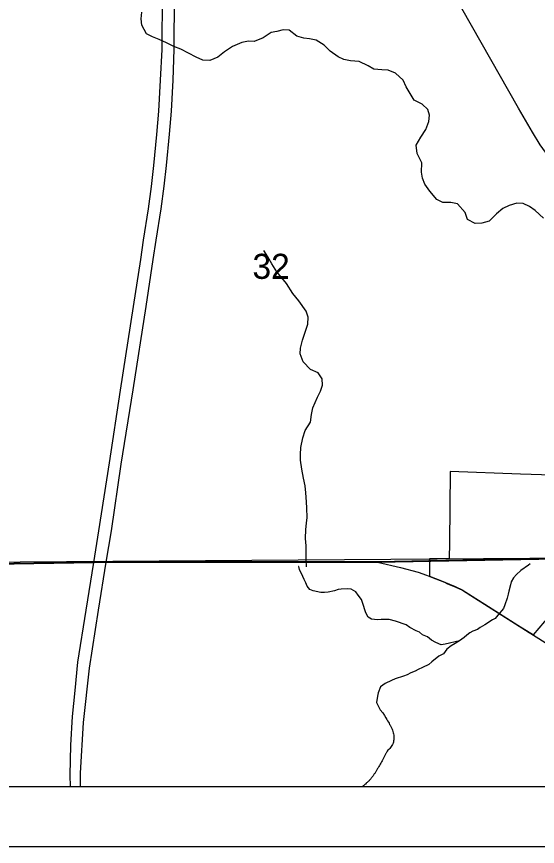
# Model space of a CAD drawing. Extents: x 0 to 36.9, y 0 to 22.
# Drawn here: x 5.318 to 6.188, y 14 to 15.386 of the extents above; entities that cross this region are included whole.
import ezdxf

# ---------------------------------------------------------------- set-up
doc = ezdxf.new("R2010")
doc.units = 0
for name, color, linetype in [('Default', 7, 'Continuous'), ('GM_X_Minor_Lake', 7, 'Continuous'), ('GM_X_Minor_River', 7, 'Continuous'), ('GM_X_Rail_Line', 7, 'Continuous'), ('GM_X_Section', 7, 'Continuous'), ('GM_X_Section_Text', 7, 'Continuous'), ('GM_X_State_Route', 7, 'Continuous'), ('GM_X_Township_Road', 7, 'Continuous'), ('SH_Cut_Line', 7, 'Continuous'), ('SH_Data', 7, 'Continuous')]:
    doc.layers.add(name, color=color, linetype=linetype)

msp = doc.modelspace()

# ---------------------------------------------------------------- linework, layer by layer
at = {"layer": 'Default'}
msp.add_lwpolyline([(6.2478, 14.6189), (6.1594, 14.6218), (6.042, 14.6259), (6.0412, 14.5072), (6.0407, 14.4806), (6.0077, 14.4801), (6.0076, 14.4514), (6.0251, 14.4445), (6.0343, 14.4407), (6.0505, 14.4341), (6.0623, 14.4284), (6.1062, 14.4008), (6.1554, 14.3696), (6.1813, 14.3532), (6.2097, 14.3868)], dxfattribs=at)
at = {"layer": 'GM_X_Minor_Lake'}
msp.add_open_spline([(5.9296, 14.2233), (5.9338, 14.2161), (5.938, 14.209), (5.9422, 14.2018), (5.9444, 14.1981), (5.9458, 14.1939), (5.9471, 14.1896), (5.9482, 14.1859), (5.9484, 14.182), (5.9479, 14.1782), (5.9474, 14.1743), (5.946, 14.1704), (5.9438, 14.1668), (5.9415, 14.1631), (5.9377, 14.1608), (5.9357, 14.1571), (5.9334, 14.1528), (5.9315, 14.1483), (5.9291, 14.144), (5.9262, 14.1388), (5.9232, 14.1337), (5.9202, 14.1286), (5.9179, 14.1247), (5.9155, 14.1209), (5.9128, 14.1172), (5.9096, 14.1126), (5.9056, 14.1087), (5.9014, 14.105), (5.8996, 14.1033), (5.8977, 14.1016), (5.8958, 14.1)], degree=3, dxfattribs=at)
at = {"layer": 'GM_X_Minor_River'}
for points in [[(5.629, 15.3132), (5.6179, 15.3183), (5.6052, 15.3245), (5.5922, 15.3312), (5.5803, 15.3359), (5.5685, 15.3418), (5.5558, 15.3476), (5.5447, 15.352), (5.5351, 15.3568), (5.5269, 15.3715), (5.526, 15.3821), (5.527, 15.3931)], [(6.1979, 15.0491), (6.184, 15.0622), (6.1744, 15.0685), (6.164, 15.0736), (6.1537, 15.0742), (6.1409, 15.0706), (6.1299, 15.0655), (6.1194, 15.0562), (6.1075, 15.0442), (6.095, 15.0406), (6.084, 15.04), (6.0713, 15.0467), (6.0669, 15.0584), (6.0541, 15.0733), (6.0431, 15.0751), (6.0298, 15.0752), (6.0198, 15.0804), (6.0082, 15.0942), (5.9996, 15.1059), (5.9957, 15.1157), (5.9944, 15.1259), (5.9949, 15.1415), (5.987, 15.1569), (5.9853, 15.1713), (5.993, 15.1847), (6.0012, 15.1974), (6.0067, 15.2104), (6.0077, 15.221), (6.0048, 15.2309), (5.9952, 15.2394), (5.9821, 15.2464), (5.9755, 15.2573), (5.9689, 15.2686), (5.9634, 15.2799), (5.951, 15.2915), (5.9388, 15.2962), (5.9281, 15.2968), (5.9148, 15.2981), (5.9052, 15.3033), (5.8902, 15.311), (5.8754, 15.3119), (5.8647, 15.3144), (5.8551, 15.3188), (5.8417, 15.328), (5.8316, 15.3381), (5.8182, 15.3463), (5.8071, 15.3487), (5.7976, 15.3497), (5.7858, 15.3533), (5.7734, 15.363), (5.7632, 15.3636), (5.7525, 15.3611), (5.7431, 15.3595), (5.7295, 15.3505), (5.7148, 15.3442), (5.7053, 15.3448), (5.6939, 15.3427), (5.6788, 15.336), (5.6653, 15.3267), (5.654, 15.3181), (5.6408, 15.3126), (5.629, 15.3132)], [(5.8019, 14.467), (5.8017, 14.4791), (5.8015, 14.492), (5.8017, 14.5022), (5.8007, 14.514), (5.8012, 14.5292), (5.8022, 14.5398), (5.8031, 14.5493), (5.8029, 14.5649), (5.8023, 14.5755), (5.8013, 14.5903), (5.7999, 14.6024), (5.7974, 14.6149), (5.7945, 14.63), (5.7923, 14.6448), (5.7921, 14.6547), (5.7927, 14.6664), (5.7962, 14.6821), (5.8002, 14.6943), (5.8087, 14.7085), (5.8103, 14.7214), (5.8128, 14.7325), (5.8204, 14.7501), (5.8256, 14.76), (5.8288, 14.7703), (5.8282, 14.7809), (5.8216, 14.7911), (5.809, 14.7962), (5.7966, 14.8092), (5.7918, 14.8224), (5.7924, 14.8319), (5.7952, 14.8456), (5.7999, 14.8586), (5.8046, 14.8724), (5.8048, 14.8841), (5.8015, 14.894), (5.7895, 14.9112), (5.7794, 14.9235), (5.7688, 14.9401), (5.7525, 14.9595), (5.7443, 14.973), (5.7373, 14.9847), (5.731, 14.9952)], [(6.1759, 14.4721), (6.1729, 14.4695), (6.1601, 14.4609), (6.153, 14.4543), (6.1478, 14.4485), (6.1441, 14.4419), (6.1427, 14.4366), (6.1402, 14.4263), (6.1388, 14.4213), (6.1374, 14.4144), (6.1335, 14.4033), (6.1313, 14.3972), (6.1216, 14.3863), (6.1175, 14.3806), (6.1127, 14.3782), (6.0999, 14.37), (6.0924, 14.3656), (6.0875, 14.3621), (6.0799, 14.3597), (6.0747, 14.3569), (6.0702, 14.3526), (6.0657, 14.3491), (6.0575, 14.3433), (6.0503, 14.339), (6.0439, 14.3347), (6.0368, 14.3296), (6.0309, 14.3215), (6.0234, 14.3179), (6.0114, 14.3085), (6.0065, 14.3039), (5.996, 14.2987), (5.9885, 14.2952), (5.9836, 14.2924), (5.9764, 14.2896), (5.9704, 14.2865), (5.964, 14.2841), (5.9504, 14.2796), (5.9443, 14.2772), (5.9334, 14.2721), (5.9255, 14.2666), (5.9219, 14.2563), (5.9205, 14.2509), (5.9188, 14.2402), (5.9251, 14.2282), (5.9296, 14.2233)], [(6.0575, 14.3433), (6.0336, 14.3379), (6.0272, 14.3366), (6.0184, 14.3403), (6.0111, 14.3443), (6.0041, 14.3499), (5.9961, 14.3535), (5.9911, 14.358), (5.9853, 14.3598), (5.9746, 14.3657), (5.9688, 14.3698), (5.9508, 14.3763), (5.9405, 14.3787), (5.936, 14.3787), (5.9314, 14.379), (5.9268, 14.3789), (5.9208, 14.3784), (5.9158, 14.3787), (5.9109, 14.3793), (5.9051, 14.383), (5.9015, 14.3902), (5.8955, 14.4072), (5.8939, 14.4121), (5.8885, 14.4196), (5.8845, 14.4253), (5.8765, 14.4297), (5.8712, 14.43), (5.8598, 14.4297), (5.8552, 14.4289), (5.8492, 14.4269), (5.8386, 14.4248), (5.8321, 14.4239), (5.8261, 14.4238), (5.8135, 14.4266), (5.8077, 14.4291), (5.8034, 14.4344), (5.8011, 14.44), (5.7983, 14.4457), (5.7963, 14.4506), (5.7907, 14.4627), (5.7891, 14.4672), (5.789, 14.4675)]]:
    msp.add_lwpolyline(points, dxfattribs=at)
at = {"layer": 'GM_X_Rail_Line'}
msp.add_lwpolyline([(5.2462, 14.4712), (5.4467, 14.4748), (5.4581, 14.475), (5.4676, 14.4751), (5.9207, 14.4754), (6.4063, 14.4846), (6.5807, 14.485), (6.7336, 14.4854), (6.7812, 14.4863), (6.8569, 14.4852), (7.1313, 14.488), (7.4027, 14.4935), (7.7356, 14.4946), (7.9858, 14.497), (8.6137, 14.5116), (8.9, 14.5158), (8.9, 20.5927)], dxfattribs=at)
msp.add_lwpolyline([(4.2643, 14.1), (8.9, 14.1), (8.9, 14.5158), (8.6137, 14.5116), (7.9858, 14.497), (7.7356, 14.4946), (7.4027, 14.4935), (7.1313, 14.488), (6.8569, 14.4852), (6.7812, 14.4863), (6.7336, 14.4854), (6.5807, 14.485), (6.4063, 14.4846), (5.9207, 14.4754), (5.4676, 14.4751), (5.4581, 14.475), (5.4467, 14.4748), (5.2462, 14.4712), (5.1185, 14.4712), (4.6008, 14.4672), (4.262, 14.4619)], close=True, dxfattribs=at)
at = {"layer": 'GM_X_Section'}
msp.add_lwpolyline([(5.2381, 15.4765), (6.2395, 15.4861), (6.2525, 14.4815), (5.2461, 14.474)], close=True, dxfattribs=at)
at = {"layer": 'GM_X_State_Route'}
for p, q in [((6.0398, 14.4771), (6.3767, 14.4835)), ((6.0101, 14.4766), (6.0398, 14.4771))]:
    msp.add_line(p, q, dxfattribs=at)
for points in [[(6.3231, 15.051), (6.2562, 15.1039), (6.2353, 15.1223), (6.2258, 15.1314), (6.2075, 15.1513), (6.1924, 15.1718), (6.1795, 15.1927), (6.1563, 15.2327), (6.0155, 15.4812), (5.8461, 15.7824), (5.7784, 15.9063), (5.7307, 15.9951), (5.6955, 16.0767), (5.6648, 16.1701), (5.6378, 16.2518), (5.6249, 16.2792), (5.5961, 16.329), (5.5806, 16.3575), (5.5514, 16.4121), (5.5432, 16.4273), (5.5369, 16.4383), (5.504, 16.4959), (5.45, 16.5871)], [(5.4469, 14.4743), (5.4553, 14.527), (5.4733, 14.6404), (5.4915, 14.7622), (5.5132, 14.9014), (5.5252, 14.9799), (5.53, 15.0124), (5.5384, 15.0647), (5.5433, 15.1023), (5.5473, 15.137), (5.5524, 15.1889), (5.5555, 15.2276), (5.5585, 15.2796), (5.5609, 15.3306), (5.5616, 15.4247)], [(5.4678, 14.4745), (5.4762, 14.5272), (5.4928, 14.6384), (5.5124, 14.7625), (5.5341, 14.9016), (5.5461, 14.9801), (5.5509, 15.0127), (5.5593, 15.065), (5.5642, 15.1025), (5.5682, 15.1372), (5.5733, 15.1892), (5.5764, 15.2278), (5.5794, 15.2798), (5.581, 15.3314), (5.5815, 15.4206)], [(4.601, 14.4666), (5.1187, 14.4707), (5.2464, 14.4707), (5.4469, 14.4743), (5.4583, 14.4745), (5.4678, 14.4745), (5.8599, 14.4748)], [(5.4077, 14.1), (5.4076, 14.119), (5.4088, 14.169), (5.4111, 14.2172), (5.4155, 14.2602), (5.4201, 14.3079), (5.4339, 14.3943), (5.4469, 14.4743)], [(5.4248, 14.1), (5.4247, 14.1225), (5.4295, 14.2069), (5.4399, 14.2977), (5.4548, 14.3946), (5.4678, 14.4745)], [(5.8599, 14.4748), (5.9209, 14.4749), (6.0101, 14.4766)]]:
    msp.add_lwpolyline(points, dxfattribs=at)
at = {"layer": 'GM_X_Township_Road'}
for points in [[(5.9209, 14.4749), (5.9593, 14.4657), (5.9886, 14.4578), (6.0025, 14.4528)], [(6.0025, 14.4528), (6.0107, 14.4498), (6.0324, 14.4411), (6.0367, 14.4393)], [(6.0367, 14.4393), (6.0518, 14.433), (6.0625, 14.4279), (6.0767, 14.419), (6.1742, 14.3572), (6.1814, 14.3527)], [(6.1814, 14.3527), (6.2576, 14.3047), (6.2802, 14.2898), (6.2859, 14.2858), (6.2925, 14.2808), (6.3024, 14.2727), (6.3109, 14.2653), (6.3169, 14.2592), (6.3377, 14.2343), (6.3777, 14.1821), (6.4006, 14.1502), (6.4157, 14.1273), (6.4254, 14.1142), (6.4347, 14.103), (6.4372, 14.1)]]:
    msp.add_lwpolyline(points, dxfattribs=at)
at = {"layer": 'SH_Cut_Line'}
for points in [[(5.2462, 14.4712), (5.4467, 14.4748), (5.4581, 14.475), (5.4676, 14.4751), (5.9207, 14.4754), (6.4063, 14.4846), (6.5807, 14.485), (6.7336, 14.4854), (6.7812, 14.4863), (6.8569, 14.4852), (7.1313, 14.488), (7.4027, 14.4935), (7.7356, 14.4946), (7.9858, 14.497), (8.6137, 14.5116), (8.9, 14.5158), (8.9, 20.9)], [(2.1, 14.1), (8.9, 14.1), (8.9, 14.5158), (8.6137, 14.5116), (7.9858, 14.497), (7.7356, 14.4946), (7.4027, 14.4935), (7.1313, 14.488), (6.8569, 14.4852), (6.7812, 14.4863), (6.7336, 14.4854), (6.5807, 14.485), (6.4063, 14.4846), (5.9207, 14.4754), (5.4676, 14.4751), (5.4581, 14.475), (5.4467, 14.4748), (5.2462, 14.4712)]]:
    msp.add_lwpolyline(points, dxfattribs=at)
at = {"layer": 'SH_Data'}
for p, q in [((2.1, 14.1), (8.9, 14.1)), ((2, 14), (9, 14))]:
    msp.add_line(p, q, dxfattribs=at)

# ---------------------------------------------------------------- texts
at = {"layer": 'GM_X_Section_Text'}
msp.add_text('32', height=0.04186, rotation=0, dxfattribs=at).set_placement((5.7119, 14.9478))

doc.saveas('drawing.dxf')
